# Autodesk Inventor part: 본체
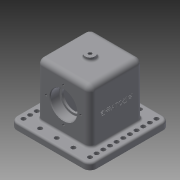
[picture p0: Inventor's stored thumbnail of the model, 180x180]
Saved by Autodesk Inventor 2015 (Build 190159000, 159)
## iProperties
Created: 2018-11
Part Number: 본체
Material: 일반
Document SubType Name: Modeling
Designer: now
Density: 1 g/cm^3
Appearance: 기본값
Author: now
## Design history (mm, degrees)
sketch "스케치1"
  geometry: L1 (-60, 60)-(60, 60); L2 (60, 60)-(60, -60); L3 (60, -60)-(-60, -60); L4 (-60, -60)-(-60, 60); L5 (-60, 60)-(60, -60); L6 (60, 60)-(-60, -60); 1 further point
  constraints: 12 end point, 2 midpoint, 2 parallel, 1 horizontal, 1 perpendicular
  dimensions: "d0" = 120 distance of L2.end L3.end; "d1" = 120 distance of L1.end L2.end
extrude "돌출1" new body sketch "스케치1" distance "d2" = 10; taper "d3" = 0 deg
sketch "스케치2"
  geometry: L1 (-40, 40)-(40, 40); L2 (40, 40)-(40, -40); L3 (40, -40)-(-40, -40); L4 (-40, -40)-(-40, 40); L5 (-40, 40)-(40, -40); L6 (40, 40)-(-40, -40); 1 further point
  constraints: 12 end point, 2 midpoint, 2 parallel, 1 horizontal, 1 perpendicular
  dimensions: "d4" = 80 distance of L2.end L3.end; "d5" = 80 distance of L1.end L2.end
extrude "돌출2" join sketch "스케치2" distance "d6" = 80; taper "d7" = 0 deg
sketch "스케치3"
  geometry: L1 (30, 23)-(-30, 23); L2 (-30, 23)-(-30, -23); L3 (-30, -23)-(30, -23); L4 (30, -23)-(30, 23); L5 (30, 23)-(-30, -23); L6 (-30, 23)-(30, -23); 1 further point
  constraints: 12 end point, 2 midpoint, 2 parallel, 1 horizontal, 1 perpendicular
  dimensions: "d8" = 46 distance of L3.end L1.start; "d9" = 60 distance of L2.end L3.end
extrude "돌출3" cut sketch "스케치3" distance "d10" = 80; taper "d11" = 0 deg
sketch "스케치4"
  geometry: L1 (100, -10)-(-20, -10) reference; C1 r 16.5 at (40, 38); 2 further points
  constraints: 1 centre point, 1 midpoint, 1 vertical alignment
  dimensions: "d12" = 33 diameter of C1; "d13" = 48 distance from line of L1 C1.centre
extrude "돌출4" cut sketch "스케치4" stored distance "d14" = 80; taper "d15" = 0 deg
sketch "스케치5"
  geometry: C1 r 16.5 at (40, 38) reference; C2 r 20 at (40, 38); 1 further point
  constraints: 1 centre point, 1 coincident
  dimensions: "d16" = 40 diameter of C2
extrude "돌출5" cut sketch "스케치5" distance "d17" = 14; taper "d18" = 0 deg
sketch "스케치6"
  geometry: C1 r 20 at (40, 38) reference; 2 further points
  constraints: 1 vertical alignment
  dimensions: "d19" = 26 distance of C1.centre point (40, 64)
hole "구멍1" sketch "스케치6" at (40, 64) diameter "d20" = 3.242; stored, may be unused: countersink angle "d24" = 90 deg, drill point angle "d26" = 118 deg; dims "d21" = 8, "d22" = 4, "d23" = 2, "d25" = 10
fillet "모깎기1" dims "d30" = 10
sketch "스케치7"
  geometry: C1 r 7.5 at (0, 0); 1 further point
  constraints: 1 centre point, 1 coincident
  dimensions: "d31" = 15 diameter of C1
extrude "돌출6" join sketch "스케치7" distance "d32" = 5; taper "d33" = 0 deg
sketch "스케치8"
  geometry: C1 r 7.5 at (0, 0) reference
hole "구멍2" sketch "스케치8" at (0, 0) diameter "d34" = 4.917; stored, may be unused: countersink angle "d38" = 90 deg, drill point angle "d40" = 118 deg; dims "d35" = 12, "d36" = 4, "d37" = 2, "d39" = 17.1
sketch "스케치9"
  geometry: L1 (10, 90)-(10, -10) reference; 3 further points
  constraints: 1 horizontal alignment, 1 midpoint, 1 other
  dimensions: "d41" = 48 distance from line of L1 point (-38, 40)
sketch "스케치10"
  geometry: A1 r 10 centre (-50, -50) between (-60, -50) and (-50, -60) reference; 1 further point
hole "구멍3" sketch "스케치10" at (-50, -50) diameter "d42" = 6.6; stored, may be unused: countersink angle "d46" = 90 deg, drill point angle "d48" = 118 deg; dims "d43" = 12, "d44" = 4, "d45" = 2, "d47" = 17.1
feature "엠보싱1" dims "d0" = 120, "d1" = 120, "d8" = 46, "d9" = 60, "d61" = 0.5, "d62" = 0
fillet "모깎기2" dims "d63" = 8
fillet "모깎기3" dims "d64" = 8
fillet "모깎기4" dims "d65" = 3
fillet "모깎기5" dims "d66" = 3
fillet "모깎기6" dims "d67" = 3
chamfer "모따기1" distance "d68" = 1; stored, may be unused: second distance "d69" = 2, angle "d70" = 45 deg
fillet "모깎기7" dims "d71" = 0.6
node "솔리드1"
pattern_circular "원형 패턴1" dims angle "d28" = 360 deg
mirror "대칭1"
pattern_linear "직사각형 패턴1" dims "d51" = 10
pattern_linear "직사각형 패턴2" dims "d57" = 25
